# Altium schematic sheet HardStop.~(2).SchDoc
size A
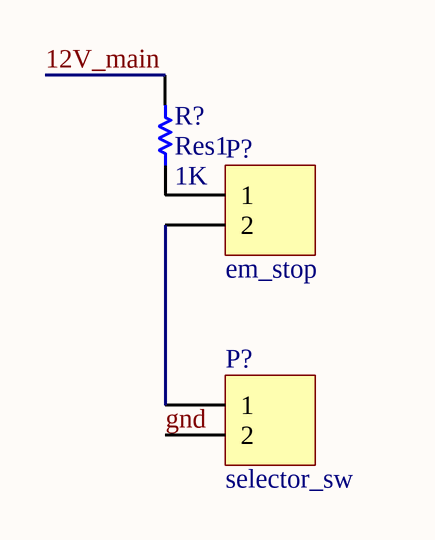
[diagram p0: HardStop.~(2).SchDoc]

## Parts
(Parts that share a designator on the sheet are numbered #1, #2 ... from top to bottom, then left to right.)
P?#1  em_stop  [HDR1X2H]
P?#2  selector_sw  [HDR1X2H]
R?  Res1  value 1K  [AXIAL-0.3]

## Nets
12V_main: R?.2
gnd: P?#2.2
NetP?#1_1: P?#1.1 R?.1
NetP?#1_2: P?#1.2 P?#2.1

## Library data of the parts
P?#1 P?#2 = Header 2H: Header, 2-Pin, Right Angle
R? = Res1: Resistor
